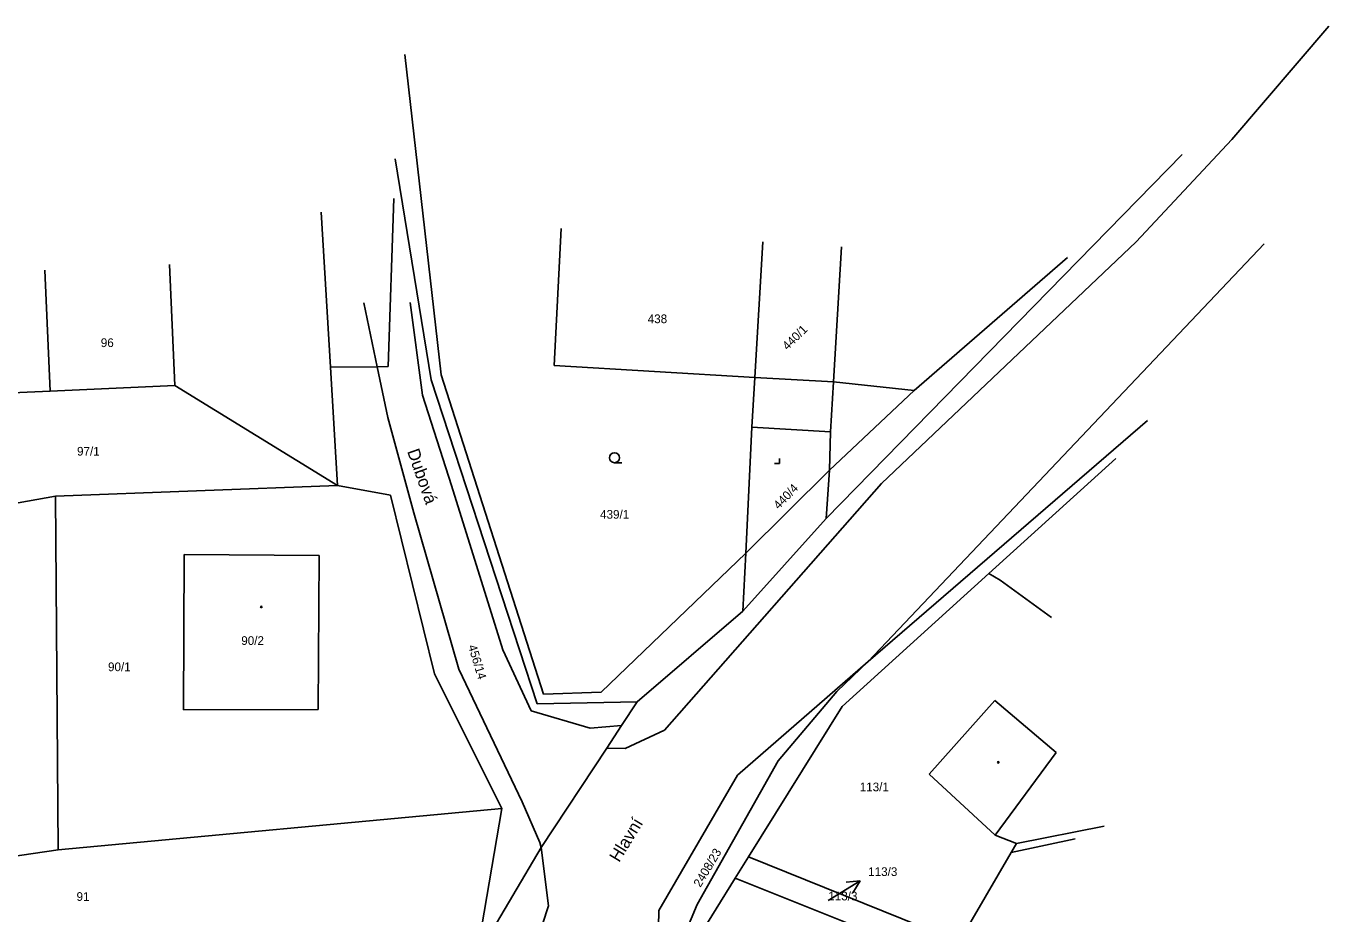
# Model space of a CAD drawing. Extents: x -454285 to -453563, y -1108687 to -1108249.
# Drawn here: x -453681.8 to -453577.1, y -1108388.1 to -1108316.7 of the extents above; entities that cross this region are included whole.
import ezdxf

# ---------------------------------------------------------------- set-up
doc = ezdxf.new("R2010")
doc.units = 0
for name, color, linetype in [('1', 7, 'Continuous'), ('14', 7, 'Continuous'), ('15', 7, 'Continuous'), ('16', 7, 'Continuous'), ('2', 7, 'Continuous'), ('23', 7, 'Continuous'), ('25', 7, 'Continuous'), ('38', 7, 'Continuous')]:
    doc.layers.add(name, color=color, linetype=linetype)

# ---------------------------------------------------------------- blocks, each defined once
blk = doc.blocks.new('Z402')
for start, end in [(0, 180), (180, 0)]:
    blk.add_arc((0, 0), 0.15, start, end)
blk = doc.blocks.new('Z3040')
blk.add_line((1.5, 0), (0, 0))
blk.add_circle((0, 1), 1)
blk = doc.blocks.new('Z319')
for p in [(-1, 0), (0, 1)]:
    blk.add_line(p, (0, 0))
blk = doc.blocks.new('Z61')
for p, q in [((0, 3), (-0.5, 2)), ((0, 0), (0, 3)), ((0, 3), (0.5, 2))]:
    blk.add_line(p, q)

msp = doc.modelspace()

# ---------------------------------------------------------------- linework, layer by layer
at = {"layer": '1'}
for p, q in [((-453649.27, -1108345.14), (-453652.15, -1108327.37)), ((-453617.52, -1108356.29), (-453588.91, -1108327.02)), ((-453652.71, -1108344.08), (-453652.26, -1108330.57)), ((-453657.36, -1108344.12), (-453658.11, -1108331.66)), ((-453638.82, -1108332.97), (-453639.37, -1108344)), ((-453623.25, -1108344.95), (-453622.61, -1108334.06)), ((-453616.93, -1108345.32), (-453616.29, -1108334.44)), ((-453657.36, -1108344.12), (-453653.61, -1108344.09)), ((-453656.79, -1108353.65), (-453657.36, -1108344.12)), ((-453653.61, -1108344.09), (-453652.71, -1108344.08)), ((-453639.37, -1108344), (-453623.25, -1108344.95)), ((-453640.75, -1108371.19), (-453649.27, -1108345.14)), ((-453623.25, -1108344.95), (-453623.49, -1108348.94)), ((-453616.93, -1108345.32), (-453617.17, -1108349.32)), ((-453679.9, -1108346.05), (-453684.29, -1108346.25)), ((-453669.86, -1108345.61), (-453679.9, -1108346.05)), ((-453669.86, -1108345.61), (-453656.79, -1108353.65)), ((-453614.14, -1108367.78), (-453591.7, -1108348.41)), ((-453623.49, -1108348.94), (-453623.97, -1108359.08)), ((-453617.17, -1108349.32), (-453623.49, -1108348.94)), ((-453617.24, -1108352.4), (-453617.17, -1108349.32)), ((-453604.44, -1108360.73), (-453594.23, -1108351.48)), ((-453617.24, -1108352.4), (-453617.52, -1108356.29)), ((-453656.79, -1108353.65), (-453679.47, -1108354.5)), ((-453656.79, -1108353.65), (-453652.54, -1108354.41)), ((-453679.47, -1108354.5), (-453683.99, -1108355.3)), ((-453679.25, -1108382.93), (-453679.47, -1108354.5)), ((-453652.54, -1108354.41), (-453649.01, -1108368.78)), ((-453624.21, -1108363.75), (-453617.52, -1108356.29)), ((-453669.13, -1108359.2), (-453669.18, -1108371.68)), ((-453658.28, -1108359.26), (-453669.13, -1108359.2)), ((-453658.28, -1108359.26), (-453658.36, -1108371.66)), ((-453623.97, -1108359.08), (-453624.21, -1108363.75)), ((-453616.22, -1108371.4), (-453604.44, -1108360.73)), ((-453603.52, -1108361.26), (-453604.44, -1108360.73)), ((-453599.41, -1108364.25), (-453603.52, -1108361.26)), ((-453624.21, -1108363.75), (-453632.71, -1108371.03)), ((-453624.64, -1108376.94), (-453614.14, -1108367.78)), ((-453649.01, -1108368.78), (-453643.59, -1108379.6)), ((-453632.71, -1108371.03), (-453640.75, -1108371.19)), ((-453632.71, -1108371.03), (-453633.96, -1108372.93)), ((-453623.75, -1108383.5), (-453616.22, -1108371.4)), ((-453609.25, -1108376.86), (-453603.95, -1108370.93)), ((-453603.95, -1108370.93), (-453599.02, -1108375.12)), ((-453658.36, -1108371.66), (-453669.18, -1108371.68)), ((-453635.16, -1108374.75), (-453633.96, -1108372.93)), ((-453640.43, -1108382.75), (-453635.16, -1108374.75)), ((-453630.96, -1108387.82), (-453624.64, -1108376.94)), ((-453603.93, -1108381.76), (-453609.25, -1108376.86)), ((-453643.59, -1108379.6), (-453679.25, -1108382.93)), ((-453643.59, -1108379.6), (-453645.41, -1108390.3)), ((-453602.22, -1108382.43), (-453603.93, -1108381.76)), ((-453602.22, -1108382.43), (-453595.18, -1108381.03)), ((-453691.56, -1108384.72), (-453679.25, -1108382.93)), ((-453640.43, -1108382.75), (-453646.47, -1108392.95)), ((-453602.66, -1108383.15), (-453597.5, -1108382.05)), ((-453602.66, -1108383.15), (-453602.22, -1108382.43)), ((-453624.82, -1108385.22), (-453623.75, -1108383.5)), ((-453623.75, -1108383.5), (-453606.84, -1108390.34)), ((-453606.84, -1108390.34), (-453602.66, -1108383.15)), ((-453627.89, -1108390.14), (-453624.82, -1108385.22)), ((-453624.82, -1108385.22), (-453608.97, -1108391.55)), ((-453631.13, -1108395.05), (-453630.96, -1108387.82))]:
    msp.add_line(p, q, dxfattribs=at)
for points in [[(-453630.51, -1108373.32), (-453613.06, -1108353.47), (-453592.59, -1108334.04), (-453584.9, -1108325.83), (-453577.11, -1108316.7)], [(-453635.16, -1108374.75), (-453633.67, -1108374.8), (-453630.51, -1108373.32)]]:
    msp.add_lwpolyline(points, dxfattribs=at)
at = {"layer": '2'}
for p, q in [((-453651.38, -1108319), (-453648.47, -1108344.74)), ((-453614.14, -1108367.78), (-453582.31, -1108334.21)), ((-453669.86, -1108345.61), (-453670.29, -1108335.87)), ((-453610.45, -1108346.01), (-453598.13, -1108335.31)), ((-453679.9, -1108346.05), (-453680.33, -1108336.32)), ((-453654.68, -1108338.95), (-453653.61, -1108344.09)), ((-453650.96, -1108338.92), (-453649.97, -1108346.39)), ((-453653.61, -1108344.09), (-453652.76, -1108348.18)), ((-453648.47, -1108344.74), (-453640.23, -1108370.42)), ((-453623.25, -1108344.95), (-453616.93, -1108345.32)), ((-453610.45, -1108346.01), (-453616.93, -1108345.32)), ((-453649.97, -1108346.39), (-453647.63, -1108353.65)), ((-453610.45, -1108346.01), (-453617.24, -1108352.4)), ((-453650.65, -1108355.84), (-453652.76, -1108348.18)), ((-453617.24, -1108352.4), (-453623.97, -1108359.08)), ((-453647.63, -1108353.65), (-453643.51, -1108366.85)), ((-453647.05, -1108368.4), (-453650.65, -1108355.84)), ((-453635.6, -1108370.26), (-453623.97, -1108359.08)), ((-453643.51, -1108366.85), (-453641.22, -1108371.75)), ((-453641.96, -1108379.07), (-453647.05, -1108368.4)), ((-453616.67, -1108370.21), (-453614.14, -1108367.78)), ((-453640.23, -1108370.42), (-453635.6, -1108370.26)), ((-453621.38, -1108375.77), (-453616.67, -1108370.21)), ((-453641.22, -1108371.75), (-453636.49, -1108373.15)), ((-453636.49, -1108373.15), (-453633.96, -1108372.93)), ((-453599.02, -1108375.12), (-453603.93, -1108381.76)), ((-453627.88, -1108387.34), (-453621.38, -1108375.77)), ((-453640.53, -1108382.34), (-453641.96, -1108379.07)), ((-453640.43, -1108382.75), (-453640.53, -1108382.34)), ((-453640.43, -1108382.75), (-453639.84, -1108387.45)), ((-453639.84, -1108387.45), (-453644.86, -1108402.86)), ((-453627.88, -1108387.34), (-453631.13, -1108395.05))]:
    msp.add_line(p, q, dxfattribs=at)

# ---------------------------------------------------------------- block references
at = {"layer": '16', "rotation": -58.65039999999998}
msp.add_blockref('Z61', (-453617.35, -1108387), dxfattribs=at)
at = {"layer": '23', "xscale": 0.4, "yscale": 0.4000000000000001}
for name, p in [('Z3040', (-453634.53, -1108351.81)), ('Z319', (-453621.26, -1108351.88))]:
    msp.add_blockref(name, p, dxfattribs=at)
at = {"layer": '25', "xscale": 0.4, "yscale": 0.4000000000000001}
for p in [(-453662.92, -1108363.4), (-453603.69, -1108375.9)]:
    msp.add_blockref('Z402', p, dxfattribs=at)

# ---------------------------------------------------------------- texts
at = {"layer": '14'}
for s, p in [('97/1', (-453677.73, -1108351.24)), ('439/1', (-453635.69, -1108356.31)), ('90/1', (-453675.24, -1108368.57)), ('113/1', (-453614.82, -1108378.23)), ('91', (-453677.77, -1108387.04)), ('113/3', (-453617.35, -1108387))]:
    msp.add_text(s, height=0.7, dxfattribs=at).set_placement(p)
for s, rotation, p in [('456/14', 286.938, (-453646.31, -1108366.56)), ('2408/23', 59.247, (-453627.63, -1108386))]:
    msp.add_text(s, height=0.7, rotation=rotation, dxfattribs=at).set_placement(p)
at = {"layer": '15'}
for s, p in [('438', (-453631.86, -1108340.59)), ('96', (-453675.82, -1108342.51)), ('90/2', (-453664.53, -1108366.46))]:
    msp.add_text(s, height=0.7, dxfattribs=at).set_placement(p)
for s, rotation, p in [('440/1', 44.577, (-453620.63, -1108342.81)), ('440/4', 46.125, (-453621.33, -1108355.61))]:
    msp.add_text(s, height=0.7, rotation=rotation, dxfattribs=at).set_placement(p)
at = {"layer": '16'}
msp.add_text('113/3', height=0.7, dxfattribs=at).set_placement((-453614.14, -1108385.04))
at = {"layer": '38'}
for s, rotation, p in [('Dubová', 289.341, (-453651.21, -1108350.89)), ('Hlavní', 58.671, (-453634.16, -1108384))]:
    msp.add_text(s, height=1, rotation=rotation, dxfattribs=at).set_placement(p)

doc.saveas('drawing.dxf')
